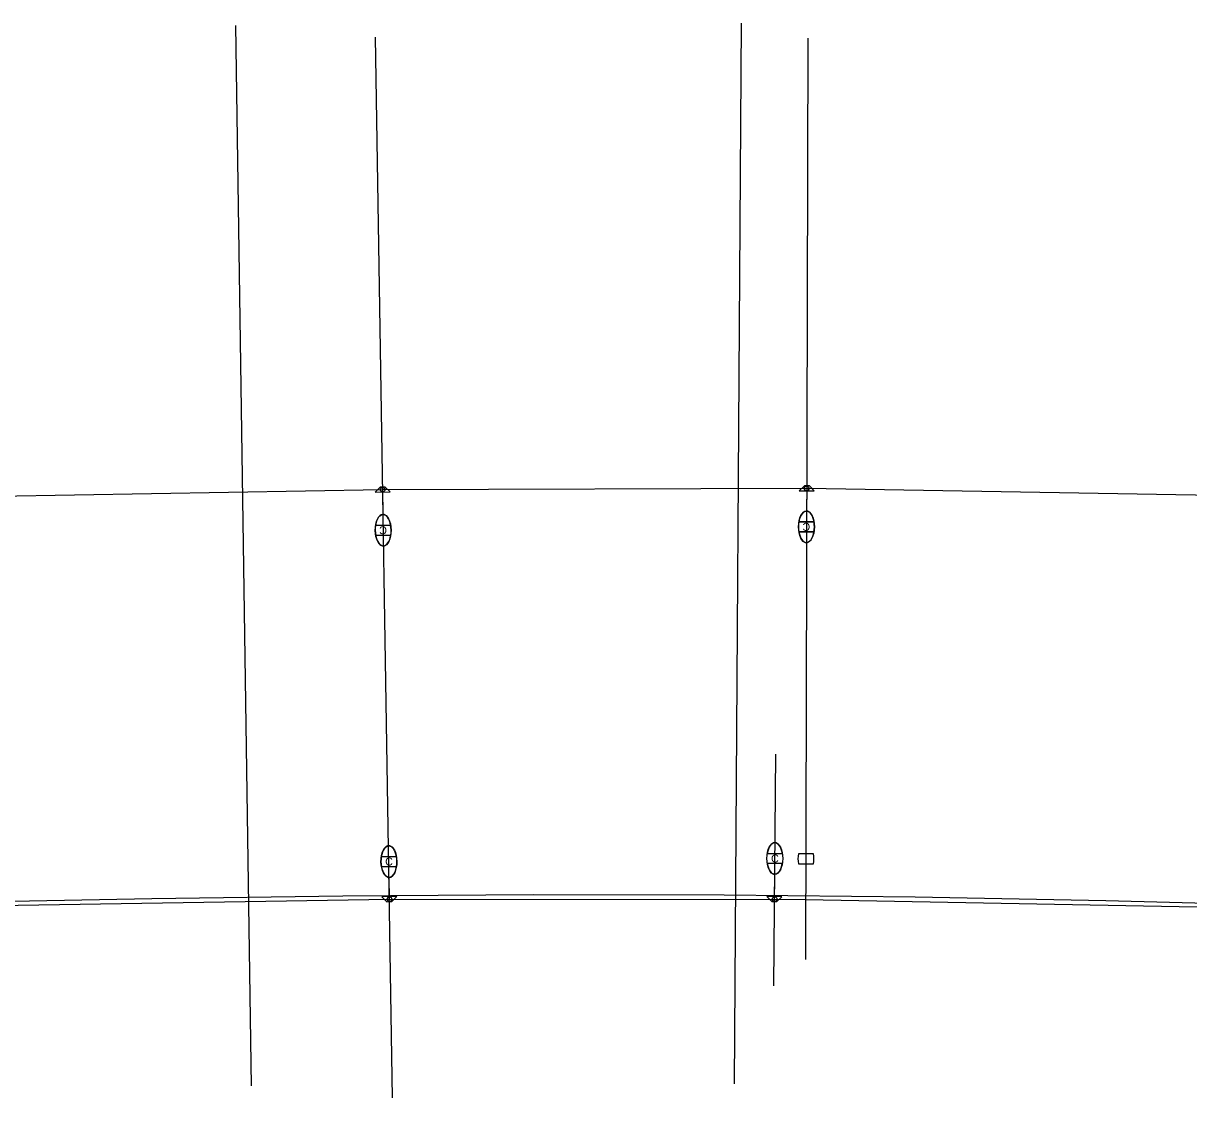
# Model space of a CAD drawing. Extents: x 915723 to 927758, y 636394 to 638609.
# Drawn here: x 923035 to 923618, y 636847 to 637385 of the extents above; entities that cross this region are included whole.
import ezdxf

# ---------------------------------------------------------------- set-up
doc = ezdxf.new("R2010")
doc.units = 0
for name, color, linetype in [('ConduitBM', 7, 'Continuous'), ('DrShaftConc', 7, 'Continuous'), ('Masonry_h', 7, 'Continuous'), ('Miscellaneous2', 7, 'Continuous'), ('PoleLight', 7, 'Continuous'), ('TextStructuresLabel', 7, 'Continuous')]:
    doc.layers.add(name, color=color, linetype=linetype)

msp = doc.modelspace()

# ---------------------------------------------------------------- linework, layer by layer
at = {"layer": 'ConduitBM'}
for p, q in [((923004.89, 637148.06), (923214.74, 637151.66)), ((923214.74, 637151.66), (923426.79, 637152.37)), ((923426.79, 637152.37), (923638.75, 637148.77)), ((923007.63, 636943.37), (923218.19, 636946.82)), ((923218.19, 636946.82), (923426.26, 636946.7)), ((923426.26, 636946.7), (923634.53, 636942.76))]:
    msp.add_line(p, q, dxfattribs=at)
at = {"layer": 'DrShaftConc'}
for p, q in [((923141.23, 637383.91), (923149.05, 636853.39)), ((923394.04, 637384.93), (923390.51, 636854.37))]:
    msp.add_line(p, q, dxfattribs=at)
msp.add_lwpolyline([(921831.32, 636923.01), (923099.42, 636947.08), (923099.42, 636947.08), (923194.81, 636948.49), (923290.21, 636949.1), (923385.61, 636948.91), (923481.01, 636947.93), (923576.4, 636946.14), (923671.76, 636943.55), (923767.11, 636940.16), (923862.42, 636935.97), (923957.69, 636930.98), (924052.92, 636925.2), (924148.09, 636918.61), (924243.21, 636911.23)], dxfattribs=at)
at = {"layer": 'Masonry_h'}
for p, q in [((923219.73, 636847.48), (923211.23, 637377.98)), ((923427.29, 637377.5), (923426.27, 636916.68)), ((923410.38, 636903.38), (923411.35, 637019.4))]:
    msp.add_line(p, q, dxfattribs=at)
at = {"layer": 'Miscellaneous2'}
for p, q in [((923218.76, 637133.9), (923211.25, 637133.79)), ((923211.25, 637133.79), (923211.25, 637133.79)), ((923430.44, 637135.51), (923422.93, 637135.56)), ((923422.93, 637135.56), (923422.93, 637135.56)), ((923211.32, 637128.79), (923218.84, 637128.9)), ((923211.32, 637128.79), (923211.32, 637128.79)), ((923422.89, 637130.56), (923422.89, 637130.56)), ((923422.89, 637130.56), (923430.41, 637130.51)), ((923221.63, 636968.15), (923214.12, 636968.04)), ((923221.63, 636968.15), (923221.63, 636968.15)), ((923422.62, 636964.52), (923430.13, 636964.47)), ((923430.17, 636969.47), (923422.65, 636969.52)), ((923430.13, 636964.47), (923430.13, 636964.47)), ((923430.17, 636969.47), (923430.17, 636969.47)), ((923214.19, 636963.04), (923221.7, 636963.15)), ((923221.7, 636963.15), (923221.7, 636963.15))]:
    msp.add_line(p, q, dxfattribs=at)
for centre, major_axis, start_param, end_param in [((923215.04, 637131.35), (-0.12, 7.92), 1.249648, 1.891946), ((923215.04, 637131.35), (-0.12, 7.92), 4.391271, 5.033538), ((923426.67, 637133.04), (0.05, 7.92), 1.249648, 1.891946), ((923426.67, 637133.04), (0.05, 7.92), 4.391271, 5.033538), ((923215.04, 637131.35), (-0.12, 7.92), 4.391241, 4.391271), ((923426.67, 637133.04), (0.05, 7.92), 4.391241, 4.391271), ((923217.91, 636965.6), (0.12, -7.92), 4.391271, 5.033538), ((923217.91, 636965.6), (0.12, -7.92), 4.391241, 4.391271), ((923217.91, 636965.6), (0.12, -7.92), 1.249648, 1.891946), ((923426.39, 636967), (-0.05, -7.92), 4.391271, 5.033538), ((923426.39, 636967), (-0.05, -7.92), 4.391241, 4.391271), ((923426.39, 636967), (-0.05, -7.92), 1.249648, 1.891946)]:
    msp.add_ellipse(centre, major_axis=major_axis, ratio=0.5, start_param=start_param, end_param=end_param, dxfattribs=at)
at = {"layer": 'PoleLight'}
for p, q in [((923214.74, 637151.68), (923214.93, 637139.27)), ((923426.8, 637152.41), (923426.72, 637140.96)), ((923211.25, 637133.79), (923218.76, 637133.9)), ((923422.93, 637135.56), (923430.44, 637135.51)), ((923218.84, 637128.9), (923211.32, 637128.79)), ((923430.41, 637130.51), (923422.89, 637130.56)), ((923214.12, 636968.04), (923221.63, 636968.15)), ((923414.59, 636964.62), (923407.07, 636964.66)), ((923407.1, 636969.66), (923414.61, 636969.62)), ((923221.7, 636963.15), (923214.19, 636963.04)), ((923410.75, 636946.84), (923410.8, 636959.22)), ((923218.19, 636946.82), (923218.03, 636957.68))]:
    msp.add_line(p, q, dxfattribs=at)
for points in [[(923216.03, 637152.96), (923213.53, 637152.93), (923211.06, 637150.41), (923218.55, 637150.49)], [(923428.11, 637153.52), (923425.61, 637153.53), (923423.1, 637151.05), (923430.6, 637151)], [(923216.88, 636945.54), (923219.38, 636945.56), (923221.86, 636948.08), (923214.36, 636948.01)], [(923409.42, 636945.58), (923411.92, 636945.56), (923414.44, 636948.04), (923406.94, 636948.1)]]:
    msp.add_lwpolyline(points, close=True, dxfattribs=at)
for centre in [(923214.74, 637151.65), (923426.78, 637152.27), (923218.19, 636946.82), (923410.75, 636946.84)]:
    msp.add_circle(centre, 1.14, dxfattribs=at)
for centre, major_axis in [((923215.04, 637131.35), (-0.12, 7.92)), ((923426.67, 637133.04), (0.05, 7.92)), ((923217.91, 636965.6), (0.12, -7.92)), ((923410.84, 636967.14), (-0.04, -7.92))]:
    msp.add_ellipse(centre, major_axis=major_axis, ratio=0.5, dxfattribs=at)
for centre, major_axis, start_param, end_param in [((923215.04, 637131.35), (-0.12, 7.92), 0, 0.847605), ((923215.04, 637131.35), (-0.12, 7.92), 5.033538, 6.283185), ((923426.67, 637133.04), (0.05, 7.92), 0, 0.847605), ((923426.67, 637133.04), (0.05, 7.92), 5.033538, 6.283185), ((923215.04, 637131.35), (-0.12, 7.92), 0.847605, 1.249648), ((923426.67, 637133.04), (0.05, 7.92), 0.847605, 1.249648), ((923215.04, 637131.35), (-0.12, 7.92), 1.891945, 4.391241), ((923426.67, 637133.04), (0.05, 7.92), 1.891945, 4.391241), ((923217.91, 636965.6), (0.12, -7.92), 1.891945, 4.391241), ((923410.84, 636967.14), (-0.04, -7.92), 1.891945, 4.391241), ((923410.84, 636967.14), (-0.04, -7.92), 5.033538, 6.283185), ((923410.84, 636967.14), (-0.04, -7.92), 0.847605, 1.249648), ((923217.91, 636965.6), (0.12, -7.92), 5.033538, 6.283185), ((923217.91, 636965.6), (0.12, -7.92), 0, 0.847605), ((923217.91, 636965.6), (0.12, -7.92), 0.847605, 1.249648), ((923410.84, 636967.14), (-0.04, -7.92), 0, 0.847605)]:
    msp.add_ellipse(centre, major_axis=major_axis, ratio=0.5, start_param=start_param, end_param=end_param, dxfattribs=at)

# ---------------------------------------------------------------- texts
at = {"layer": 'TextStructuresLabel'}
for rotation, p in [(180.84473, (923216.89, 637133.37)), (179.61845, (923428.55, 637135.03)), (0.84473, (923216.07, 636963.57)), (359.73477, (923408.96, 636965.15))]:
    msp.add_text('C', height=4, rotation=rotation, dxfattribs=at).set_placement(p)

doc.saveas('drawing.dxf')
